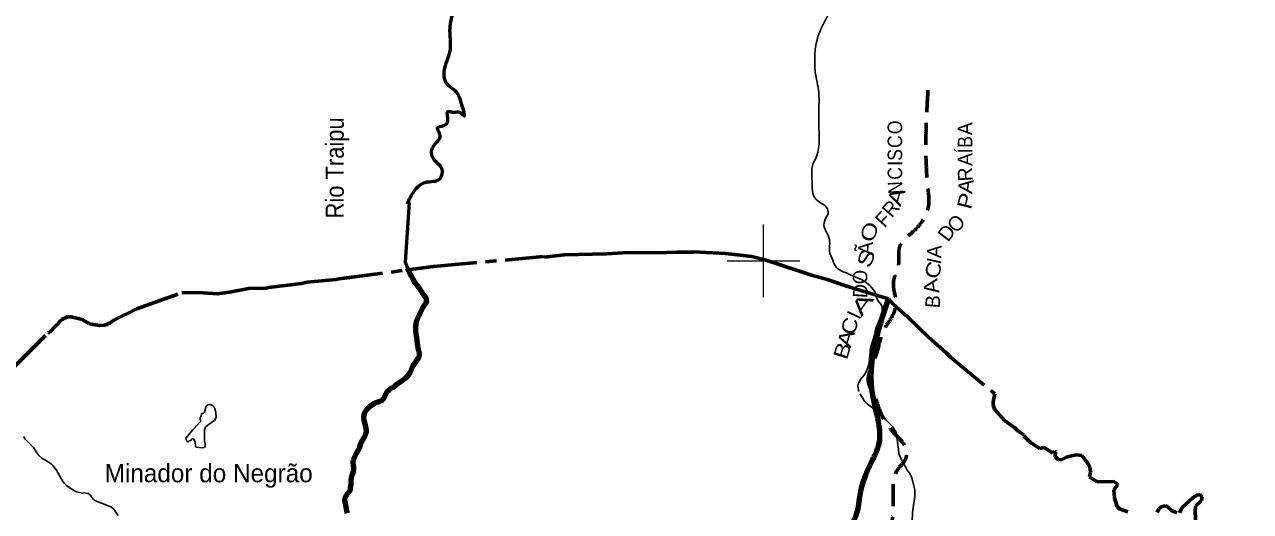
# Model space of a CAD drawing. Extents: x 553962 to 842807, y 8883888 to 9032388.
# Drawn here: x 729677 to 763398, y 8968113 to 8981489 of the extents above; entities that cross this region are included whole.
import ezdxf
from ezdxf.enums import TextEntityAlignment as Align

# ---------------------------------------------------------------- set-up
doc = ezdxf.new("R2010")
doc.units = 0
doc.header["$LTSCALE"] = 200
doc.linetypes.add('LONG_DASH_SHORT_DASH', pattern=[9.9, 6, -1.2, 1.5, -1.2])
doc.linetypes.add('MEDIUM_DASHED', pattern=[4.5, 3, -1.5])
for name, color, linetype, lineweight in [('10', 7, 'MEDIUM_DASHED', 60), ('12', 7, 'Continuous', 25), ('2', 7, 'Continuous', 13), ('21', 7, 'Continuous', 25), ('24', 7, 'Continuous', 25), ('7', 7, 'LONG_DASH_SHORT_DASH', 60), ('9', 7, 'Continuous', 90)]:
    doc.layers.add(name, color=color, linetype=linetype, lineweight=lineweight)
doc.layers.add('41', color=7, linetype='Continuous')
doc.layers.add('49', color=7, linetype='Continuous')

msp = doc.modelspace()

# ---------------------------------------------------------------- linework, layer by layer
at = {"layer": '10'}
msp.add_spline([(753353.8, 8967411.3), (753402.1, 8967459.7), (753447.5, 8967537.9), (753569.9, 8968137.4), (753569.9, 8968618.2), (753685.3, 8969252.9), (753896.8, 8969522.2), (753935.3, 8969791.5), (753646.8, 8970214.6), (753242.9, 8970791.6), (753050.6, 8971291.7), (752896.7, 8971618.7), (753127.5, 8972484.2), (753300.6, 8973080.5), (753550.6, 8973484.4), (753646.8, 8973869.1), (753589.1, 8974215.3), (753589.1, 8974484.5), (753704.5, 8974811.5), (753723.7, 8975177), (753762.2, 8975427), (754089.2, 8975773.2), (754377.7, 8976100.2), (754550.8, 8976561.8), (754531.6, 8976946.5), (754538.8, 8979865.5)], degree=3, dxfattribs=at)
at = {"layer": '12'}
for points in [[(752444.7, 8974591.9), (752707.4, 8974475.5), (752786.5, 8974428), (752930.8, 8974317.1), (753062.6, 8974152.6), (753117.5, 8973959.1), (753180.2, 8973867.8), (753242.2, 8973795.8), (753262.4, 8973756.4), (753269, 8973717.7), (753270.2, 8973648.7), (753257.3, 8973562.4), (753237.5, 8973498.7), (753090.9, 8973141.2), (753070.7, 8973063.5), (753072.3, 8973000.7), (753069.1, 8972980.9), (752948.8, 8972607.6), (752907.8, 8972182.6), (752892.3, 8972118.5), (752847.2, 8971998.1), (752793, 8971880.4), (752680.5, 8971744), (752622, 8971655), (752613.9, 8971634.4), (752600.5, 8971552.9), (752626, 8971408.9)], [(752664, 8971340.7), (752771, 8971148.4), (752859.2, 8971072.4), (753072.2, 8970907.4), (753319.1, 8970681.2), (753384.5, 8970609.5), (753558.8, 8970434.3), (753589.6, 8970386.1)], [(753589.6, 8970386.1), (753640.4, 8970306.5), (753650.2, 8970274.2), (753691.1, 8970026.8), (753698.8, 8969944.5), (753719.3, 8969828.1), (753728.3, 8969699.4), (753756.5, 8969629.3), (753798.1, 8969540.9)], [(753798.1, 8969540.9), (753859.8, 8969409.4), (753909.1, 8969336.8), (753959.2, 8969249.6), (754012.5, 8969179), (754046.6, 8969117.8), (754069.8, 8969065.7), (754101.8, 8968966.1), (754161.6, 8968706.3), (754168.3, 8968520.8), (754116.9, 8968213), (754102.8, 8968082.3), (754094.2, 8967837.6), (754098.2, 8967608.9), (754095, 8967556.7), (754045.7, 8967185.6), (754028.2, 8966994.8), (754035.8, 8966766.1), (754034.7, 8966701.8), (754052, 8966621.5), (754053.6, 8966322.7), (754067.7, 8966231)]]:
    msp.add_lwpolyline(points, dxfattribs=at)
msp.add_spline([(752444.7, 8974591.9), (752220.7, 8974690.3), (751998.9, 8974824.7), (751911.5, 8975012.9), (751817.4, 8975268.3), (751824.1, 8975476.7), (751783.8, 8975691.7), (751676.2, 8975920.3), (751696.4, 8976135.3), (751783.8, 8976316.8), (751743.5, 8976458), (751541.8, 8976612.5), (751387.2, 8976773.8), (751340.2, 8977083), (751333.5, 8977432.5), (751346.9, 8977600.6), (751441, 8977812.6), (751535.1, 8978263.1), (751521.7, 8978828), (751528.4, 8979271.8), (751521.7, 8979621.5), (751427.6, 8980193.1), (751414.1, 8980616.7), (751461.2, 8981006.8), (751622.5, 8981450.6), (751723.3, 8981645.6), (752140.5, 8982419.4)], degree=3, dxfattribs=at)
at = {"layer": '2'}
for p, q in [((750000, 8974000), (750000, 8976000)), ((749000, 8975000), (751000, 8975000))]:
    msp.add_line(p, q, dxfattribs=at)
at = {"layer": '21'}
for points in [[(734441.2, 8970498.9), (734303.8, 8970355.7), (734116.5, 8970129.9), (734113.1, 8970114.7), (734119.4, 8970075.5), (734145.2, 8970051.2), (734168.9, 8970019.5), (734181.4, 8970021.5), (734206.5, 8970050.8), (734247.2, 8970065.8), (734290.4, 8970107.4), (734303.5, 8970111.7), (734321.8, 8970111.1), (734333.6, 8970097.9), (734375, 8970020.5), (734381.7, 8969909.7), (734389.7, 8969884.2), (734396.2, 8969874.8), (734551.2, 8969860.5), (734613.7, 8969866.7), (734627.4, 8969872.6), (734648.3, 8969912.4), (734649.6, 8969980.8), (734634.3, 8970019.7), (734630.8, 8970039.7), (734623.8, 8970209), (734629.4, 8970357.2), (734643.8, 8970405.7), (734658.9, 8970427.2), (734730.6, 8970496.3), (734782.1, 8970530.8), (734817.5, 8970561.3), (734855.2, 8970579.8), (734904.2, 8970611.7), (734951.1, 8970691.3), (734935.8, 8970827.7), (734908.4, 8970936.3), (734891.3, 8970974.5), (734841.3, 8971037.1), (734782.7, 8971051.2)], [(734782.7, 8971051.2), (734756.2, 8971050.8), (734720.8, 8971040.1), (734672, 8971001.4), (734663.3, 8970981.6), (734624.9, 8970837.4), (734592.1, 8970806.3), (734562.4, 8970812), (734543.6, 8970783.7), (734532, 8970740.5), (734512.6, 8970689.2), (734508.8, 8970650.1), (734519.5, 8970599.8), (734514.8, 8970584.3), (734441.2, 8970498.9)]]:
    msp.add_lwpolyline(points, dxfattribs=at)
at = {"layer": '24', "lineweight": 53}
for points in [[(740256.1, 8976602), (740150, 8974957.6), (740199.7, 8974820.8)], [(740199.7, 8974820.8), (740238.1, 8974727.3), (740279.6, 8974643.7), (740334, 8974546.8), (740357.2, 8974493.5), (740382.9, 8974446.8), (740484.1, 8974309.5), (740613.7, 8974119.1), (740717.4, 8973990.4), (740732.3, 8973856.4), (740732.3, 8973856.4), (740732.3, 8973856.4), (740732.3, 8973856.4), (740618, 8973688.2), (740487, 8973417.6), (740453.4, 8973331.1), (740434.4, 8973194.5), (740433.5, 8973090.3), (740439.6, 8973000.5), (740466.4, 8972816.9), (740475.8, 8972719.9), (740503, 8972572.4), (740529.6, 8972497.6), (740528.8, 8972385.3), (740511.7, 8972342.2), (740484.3, 8972292.1), (740351.8, 8972095.1), (740271.5, 8971918), (740212.1, 8971832.2), (740155.8, 8971771.6), (740084.9, 8971712.7), (739981.4, 8971647.3), (739910.7, 8971596.4), (739837.5, 8971524.6), (739757.3, 8971490.6), (739708.7, 8971453.2), (739664.3, 8971410.8), (739632.6, 8971371.3), (739561.2, 8971230.5), (739523.3, 8971179.7), (739487, 8971150), (739449.3, 8971129.7), (739395.4, 8971112.6), (739333.7, 8971101.4), (739290.2, 8971081), (739173.2, 8970993.1), (739094.9, 8970916.4), (739054.2, 8970867.5), (739009.7, 8970790), (739003.8, 8970676.8), (739015.8, 8970579.9), (739051.5, 8970450.1), (739063.7, 8970387.4), (739071.4, 8970367.8), (739072.7, 8970313.5), (739066, 8970263.1), (739051.2, 8970216.4), (739028.1, 8970169.5), (738938.6, 8970019), (738921.2, 8969978.8), (738878.8, 8969842.3), (738791.5, 8969691.8), (738791.5, 8969691.8), (738733.8, 8969568.4), (738716.4, 8969521.7)], [(738716.4, 8969521.7), (738712.1, 8969454.1), (738717.3, 8969381.7), (738726.3, 8969324), (738727.4, 8969273.7), (738715.5, 8969198), (738691.5, 8969119), (738673.7, 8969086.8), (738662.6, 8969043.4), (738652.4, 8968953.5), (738651, 8968849.4), (738637.2, 8968762.8), (738633.9, 8968702.3), (738619.6, 8968671), (738536.5, 8968568.4), (738527.1, 8968550.9), (738521.9, 8968529), (738494.8, 8968495.2), (738481.7, 8968447.9), (738480.1, 8968427.4), (738500, 8968342), (738533.5, 8968133), (738555.2, 8968065.6)]]:
    msp.add_lwpolyline(points, dxfattribs=at)
at = {"layer": '24'}
msp.add_lwpolyline([(729657.8, 8970174.1), (729686.6, 8970110.8), (729928.3, 8969870.5), (730012.4, 8969726.4), (730069.7, 8969653.9), (730149.2, 8969579.5), (730284.8, 8969503.9), (730412, 8969418.7), (730463.2, 8969367.6), (730567.7, 8969229.8), (730688.7, 8969016.5), (730730.3, 8968933.7), (730772.2, 8968877.4), (730829.8, 8968823.3), (731008.2, 8968703.6), (731105.3, 8968654.8), (731233, 8968624.6), (731360.6, 8968619.3), (731432.2, 8968607.5), (731490.4, 8968564.6), (731529, 8968498.9), (731572, 8968444.1), (731629.2, 8968401.6), (732006.1, 8968259.5), (732068.7, 8968231.4), (732130.1, 8968177.5), (732172.3, 8968124.3), (732254.1, 8968003.8)], dxfattribs=at)
for points in [[(771983.6, 8980431.6), (771458.1, 8980369.7), (771148.9, 8980648.1), (771087.1, 8980988.4), (770932.5, 8981297.7), (770808.9, 8981638), (770345.2, 8981761.8), (770005.1, 8981885.5), (769819.6, 8982071.1), (769634.1, 8981854.6), (769479.5, 8982009.2), (769015.8, 8982318.6), (768923.1, 8982689.8), (768706.7, 8982937.2), (768593.5, 8983157.4), (768713.2, 8983415.3), (768842, 8983516.6), (768842, 8983590.2), (768630.3, 8983700.8), (768289.8, 8983940.2), (768207, 8984262.5), (768022.9, 8984465.2), (767700.8, 8984557.2), (767590.3, 8984640.1), (767553.5, 8985036.1), (767599.5, 8985266.4), (767599.5, 8985422.9), (767461.5, 8985607.1), (767314.2, 8985634.8), (767268.2, 8985533.4), (767139.4, 8985496.6), (766918.5, 8985616.3), (766789.6, 8985818.9), (766559.5, 8985957.1), (766219, 8986297.8), (765850.9, 8986500.4), (765363.1, 8986924.1), (764801.7, 8987504.3), (764663.6, 8987624), (764378.3, 8988066), (764295.5, 8988259.4), (764221.8, 8988296.3), (764083.8, 8988204.2), (763982.5, 8988268.6), (763669.6, 8988664.7), (763586.8, 8988683.1), (763540.8, 8988848.8), (763605.2, 8988913.3), (763665, 8988922.5), (763720.2, 8989088.3), (763554.6, 8989254.1), (763480.9, 8989475.1), (763628.2, 8989677.7), (763977.9, 8989935.6), (764143.6, 8990101.3), (764125.2, 8990285.5), (763849.1, 8990377.6), (763793.9, 8990525), (763591.4, 8990617.1), (763480.9, 8990635.5), (763260.1, 8990525), (763094.4, 8990525), (762965.5, 8990635.5), (762818.3, 8990856.5), (762781.5, 8990930.2), (762652.6, 8990967), (762450.1, 8991169.6), (762082, 8991335.4), (761916.3, 8991464.3), (761750.7, 8991464.3), (761640.2, 8991261.7), (761456.2, 8991059.1), (761382.5, 8990967), (761290.5, 8990948.6), (761198.5, 8991059.1), (761143.2, 8991298.6), (760867.1, 8991464.3), (760738.3, 8991666.9), (760499, 8991795.9), (760351.7, 8992035.3), (760094, 8992495.8), (759854.7, 8992403.7), (759652.3, 8992256.3), (759394.6, 8992477.3), (758971.2, 8992643.1), (758731.9, 8992753.6), (758639.9, 8993048.3), (758566.2, 8993324.6), (758695.1, 8993508.8), (758916, 8993453.6), (758879.2, 8993619.3)], [(715037, 8973071.8), (715705.1, 8973746.2), (715968.5, 8974273.5), (716313.1, 8974881.9), (716799.5, 8975226.6), (717083.2, 8975429.4), (717285.9, 8975328), (717752, 8975003.5), (717934.4, 8974821), (718137.1, 8974800.7), (718522.2, 8975145.5), (718826.2, 8975165.8), (718927.5, 8975307.7), (719251.8, 8975287.5), (719596.3, 8975855.3), (719799, 8976301.5), (720042.2, 8976686.8), (720771.8, 8977072.1), (721197.4, 8977051.8), (721481.2, 8977356), (721987.8, 8977396.6), (722291.8, 8977356), (722514.8, 8977639.9), (722859.3, 8978086.1), (723244.4, 8978309.2), (723548.4, 8978795.9), (723507.9, 8979566.5), (723426.8, 8979749.1), (723730.8, 8980235.8), (724115.9, 8980418.3), (724501, 8980803.6), (724886, 8981067.2), (724886, 8981594.5), (724865.8, 8981939.3), (725068.4, 8982385.5), (725169.8, 8982831.6), (725331.9, 8983216.9), (725311.6, 8983582), (725473.8, 8983825.3), (725696.7, 8983987.6), (725777.8, 8984433.7), (725858.8, 8984636.5), (726183.1, 8984636.5), (726162.8, 8984920.5), (726284.5, 8985163.8), (726588.5, 8985569.4), (726993.8, 8986056.1), (726770.9, 8986299.5), (726466.9, 8986238.7), (726264.2, 8986340.1), (726527.7, 8986563.1), (726487.1, 8986745.7), (726770.9, 8986907.9), (727155.9, 8987090.4), (727297.8, 8987171.5), (727338.3, 8987496), (727581.6, 8987698.8), (727743.7, 8987921.9), (727905.8, 8988084.1), (728068, 8988408.6), (728351.7, 8988510), (728453, 8988814.2), (728655.7, 8988854.8), (728676, 8989098.1), (728898.9, 8989260.4), (729121.8, 8989260.4), (729284, 8989037.3), (729527.2, 8988733.1), (729750.1, 8988712.8), (729973.1, 8988834.5), (729993.3, 8988753.4), (730054.1, 8988530.3), (730135.2, 8988469.4), (730358.1, 8988469.4), (730459.5, 8988408.6), (730702.7, 8988489.7), (730702.7, 8988611.4), (730885.1, 8988652), (731067.5, 8988469.4), (731168.8, 8988347.8), (731472.8, 8988368), (731736.3, 8988631.7), (731857.9, 8988834.5), (732222.7, 8988814.2), (732324, 8989017), (732506.4, 8989138.7), (732547, 8989300.9), (732851, 8989402.3), (733073.9, 8989382), (733114.4, 8989666), (733215.8, 8989848.5)]]:
    msp.add_spline(points, degree=3, dxfattribs=at)
at = {"layer": '24', "lineweight": 53}
msp.add_spline([(740207.8, 8976565.1), (740390.3, 8976909.9), (740694.3, 8977153.2), (741099.6, 8977254.6), (741160.4, 8977518.3), (741038.8, 8977680.5), (740876.7, 8977923.9), (740998.3, 8978248.3), (741099.6, 8978370), (741099.6, 8978471.4), (741038.8, 8978653.9), (741200.9, 8978714.8), (741322.5, 8978836.5), (741322.5, 8979100.1), (741484.7, 8979079.8), (741646.8, 8979079.8), (741768.4, 8978978.4), (741707.6, 8979282.6), (741525.2, 8979667.9), (741302.3, 8979850.5), (741221.2, 8980215.5), (741383.3, 8980763.1), (741383.3, 8981209.2), (741383.3, 8981432.3), (741991.3, 8982770.8), (742356.2, 8983723.9), (742417, 8984271.5), (742741.2, 8985042.1), (742903.4, 8985812.8), (743106, 8986218.4), (743470.8, 8986380.6), (743734.3, 8986887.6), (743734.3, 8987354.1), (744038.3, 8987354.1), (744322.1, 8987658.2), (744342.3, 8987881.3), (744524.7, 8988145), (744686.9, 8988266.7), (744849, 8988408.6), (745031.4, 8988347.8), (745274.6, 8988205.8), (745416.5, 8988205.8), (745598.9, 8988388.3), (745659.7, 8988631.7)], degree=3, dxfattribs=at)
at = {"layer": '7'}
for points in [[(729404.2, 8972096.7), (730321.7, 8973018.8), (730368.4, 8973026), (730699.4, 8973383.6), (730862, 8973459.9), (730956.1, 8973460), (731265.8, 8973385.6), (731447.8, 8973274.4), (731473.6, 8973278.5), (731501.8, 8973259.3), (731752.1, 8973224.9), (731885.4, 8973232.8), (732033.3, 8973290.9), (732132.7, 8973369.8), (732767.6, 8973679.2), (734004.4, 8974123.6), (734587.5, 8974117.1), (734986.3, 8974093.8), (735372.7, 8974147.2), (735835.4, 8974235.1), (736327.4, 8974244.9), (736385.3, 8974265.2), (737292.2, 8974376.7), (737450.9, 8974411), (738250.7, 8974481.5), (738334.6, 8974505.4), (740923.3, 8974839.9), (743944.6, 8975116), (743973.3, 8975101.7), (744524.3, 8975159.5), (745697.7, 8975189)], [(745697.7, 8975189), (745697.7, 8975189), (746278.3, 8975226), (747060.9, 8975214.3), (747626.8, 8975234.9), (748067.1, 8975233), (748078.4, 8975249.4), (748961.7, 8975196.1), (749681.4, 8975121.3), (750036, 8975026.7), (750271.4, 8974951.8), (751320.7, 8974608), (751750.1, 8974483.8), (752242.5, 8974318.8), (752380.7, 8974278), (753439.5, 8973954.2), (753583.6, 8973799.8), (753961.2, 8973460.6), (754538, 8972903.3), (755030, 8972474.8), (755147.7, 8972349.6), (756362.8, 8971344), (756320.3, 8971125.1), (756323.8, 8971036.6), (756361.2, 8970920.9), (756631.5, 8970616), (756915, 8970410.1), (757002.6, 8970325.1), (757165.2, 8970215.8), (757167.7, 8970190.1), (757348.9, 8970005.6), (757600.5, 8969846.9), (757701.3, 8969872.7), (757754.8, 8969855.7), (757962.9, 8969718.5), (758005.2, 8969765.2), (758038.1, 8969737.6), (758029.7, 8969624), (758115.6, 8969531.9), (758205.5, 8969542.5), (758357.8, 8969613.2), (758603.6, 8969671), (758755.3, 8969645.6), (758888.7, 8969481.4), (758982.7, 8969336.6), (758994.5, 8969195.7), (758967.2, 8969062.8), (759180.8, 8968923.9), (759628.7, 8968933.4), (759730, 8968884.3), (759736.6, 8968843), (759642.6, 8968697.4), (759656.2, 8968476.3), (759734.5, 8968249.9), (759797.4, 8968186.8), (760020.8, 8968100.7)], [(761447, 8968077.5), (761506.1, 8968210.7), (761825.6, 8968499.9), (761961, 8968579.3), (762052.9, 8968547.4), (762065.9, 8968514.3), (762049.6, 8968410.7), (761891.1, 8968267.7), (761875.3, 8968158.2), (761883.2, 8967876.5)], [(760833.6, 8968087.2), (760876.7, 8968185), (760939.1, 8968243.5), (761053, 8968271), (761107.6, 8968247.7), (761221.6, 8968138.1), (761368.5, 8968077.3)]]:
    msp.add_lwpolyline(points, dxfattribs=at)
at = {"layer": '9'}
for points in [[(740210.1, 8974795.4), (740238.1, 8974727.3), (740279.6, 8974643.7), (740334, 8974546.8), (740357.2, 8974493.5), (740382.9, 8974446.8), (740484.1, 8974309.5), (740613.7, 8974119.1), (740717.4, 8973990.4), (740732.3, 8973856.4), (740732.3, 8973856.4), (740732.3, 8973856.4), (740732.3, 8973856.4), (740618, 8973688.2), (740487, 8973417.6), (740453.4, 8973331.1), (740434.4, 8973194.5), (740433.5, 8973090.3), (740439.6, 8973000.5), (740466.4, 8972816.9), (740475.8, 8972719.9), (740503, 8972572.4), (740529.6, 8972497.6), (740528.8, 8972385.3), (740511.7, 8972342.2), (740484.3, 8972292.1), (740351.8, 8972095.1), (740271.5, 8971918), (740212.1, 8971832.2), (740155.8, 8971771.6), (740084.9, 8971712.7), (739981.4, 8971647.3), (739910.7, 8971596.4), (739837.5, 8971524.6), (739757.3, 8971490.6), (739708.7, 8971453.2), (739664.3, 8971410.8), (739632.6, 8971371.3), (739561.2, 8971230.5), (739523.3, 8971179.7), (739487, 8971150), (739449.3, 8971129.7), (739395.4, 8971112.6), (739333.7, 8971101.4), (739290.2, 8971081), (739173.2, 8970993.1), (739094.9, 8970916.4), (739054.2, 8970867.5), (739009.7, 8970790), (739003.8, 8970676.8), (739015.8, 8970579.9), (739051.5, 8970450.1), (739063.7, 8970387.4), (739071.4, 8970367.8), (739072.7, 8970313.5), (739066, 8970263.1), (739051.2, 8970216.4), (739028.1, 8970169.5), (738938.6, 8970019), (738921.2, 8969978.8), (738878.8, 8969842.3), (738791.5, 8969691.8), (738791.5, 8969691.8), (738733.8, 8969568.4), (738716.4, 8969521.7)], [(738716.4, 8969521.7), (738712.1, 8969454.1), (738717.3, 8969381.7), (738726.3, 8969324), (738727.4, 8969273.7), (738715.5, 8969198), (738691.5, 8969119), (738673.7, 8969086.8), (738662.6, 8969043.4), (738652.4, 8968953.5), (738651, 8968849.4), (738637.2, 8968762.8), (738633.9, 8968702.3), (738619.6, 8968671), (738536.5, 8968568.4), (738527.1, 8968550.9), (738521.9, 8968529), (738494.8, 8968495.2), (738481.7, 8968447.9), (738480.1, 8968427.4), (738500, 8968342), (738533.5, 8968133), (738555.2, 8968065.6)]]:
    msp.add_lwpolyline(points, dxfattribs=at)
msp.add_spline([(750521.5, 8957798.6), (750290, 8958657.6), (749980, 8960173.9), (749746.6, 8961538.9), (749919.1, 8962982.1), (750673.6, 8964858.9), (751354.2, 8966153.2), (751832.9, 8967092.2), (752515.2, 8967905.8), (752689.9, 8968716.5), (752991.6, 8969502.6), (753167.8, 8969908.5), (753010.5, 8971299.2), (753439.5, 8973954.2)], degree=3, dxfattribs=at)

# ---------------------------------------------------------------- texts
at = {"layer": '10'}
for s, rotation, width, p in [('O', 90.036, 0.9, (753817.8, 8978665.2)), ('C', 90.036, 0.9, (753818, 8978272.4)), ('B', 90.036, 0.9, (755746.5, 8978265.8)), ('S', 90.036, 0.9, (753818.2, 8977908.6)), ('Í', 90.036, 0.85, (755746.7, 8978022)), ('C', 90.036, 0.9, (753818.6, 8977399.4)), ('N', 92.943, 0.9, (753827.9, 8977019.2)), ('A', 83.512, 1.1, (755762.6, 8977022)), ('A', 72.093, 1.35, (753844.7, 8976698.2)), ('P', 75.752, 1.2, (755758.5, 8976597.7)), ('O', 68.654, 1.3, (753100.6, 8975721.6)), ('S', 68.232, 1.35, (753011.4, 8974993.7)), ('O', 92.819, 0.95, (752858.4, 8974562.2)), ('C', 75.108, 1.2, (754866.1, 8974693.7)), ('A', 99.428, 1.15, (754812.1, 8974324.5)), ('A', 54.756, 1.75, (752879.4, 8973696.6)), ('C', 73.461, 1.2, (752562.8, 8973151.1)), ('A', 74.159, 1.3, (752463.3, 8972809.8)), ('B', 72.657, 1.25, (752362.1, 8972471.4))]:
    msp.add_text(s, height=400, rotation=rotation, dxfattribs=dict(at, width=width)).set_placement(p, align=Align.CENTER)
for s, rotation, p in [('A', 90.036, (755746.3, 8978627.4)), ('I', 90.036, (753818.4, 8977676.6)), ('A', 90.036, (755746.8, 8977783.2)), ('R', 92.943, (755748.6, 8977384.2)), ('F', 47.713, (753441.2, 8976008.7)), ('R', 49.429, (753655.3, 8976304.3)), ('O', 47.713, (755448.4, 8975892)), ('D', 52.701, (755198, 8975649.5)), ('Ã', 87.425, (753008, 8975336.6)), ('A', 87.425, (754900.6, 8975243.2)), ('I', 77.053, (754893.2, 8974952.8)), ('D', 86.239, (752868.5, 8974156.8)), ('B', 86.239, (754860, 8973866)), ('I', 64.893, (752674.8, 8973428.8))]:
    msp.add_text(s, height=400, rotation=rotation, dxfattribs=at).set_placement(p, align=Align.CENTER)
at = {"layer": '41'}
msp.add_text('Minador do Negrão', height=500, dxfattribs=at).set_placement((731880.7, 8968914.6))
at = {"layer": '49', "width": 0.9}
msp.add_text('Rio Traipu', height=500, rotation=90, dxfattribs=at).set_placement((738459.1, 8977551.3), align=Align.CENTER)

doc.saveas('drawing.dxf')
